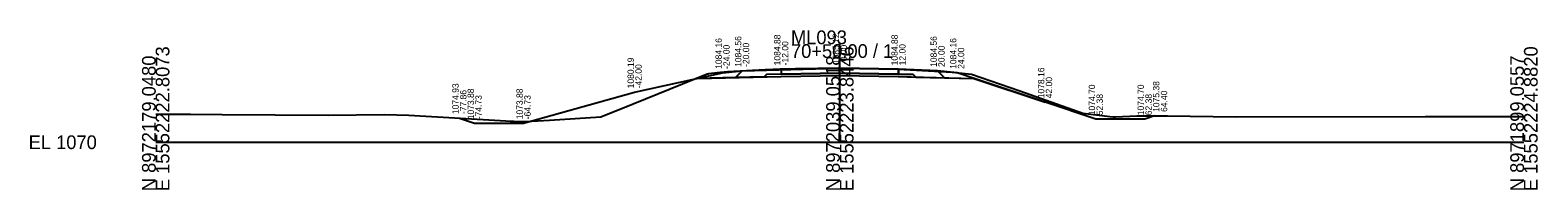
# Model space of a CAD drawing. Extents: x -26 to 14283, y -10 to 28.
# Drawn here: x 9974.3 to 10282.8, y -9.7 to 22.8 of the extents above; entities that cross this region are included whole.
import ezdxf

# ---------------------------------------------------------------- set-up
doc = ezdxf.new("R2010")
doc.units = 0
for name, color, linetype in [('Default', 7, 'Continuous'), ('dsn3DCenterLine', 7, 'Continuous'), ('dsn3DDitchBack', 7, 'Continuous'), ('dsn3DDitchFront', 7, 'Continuous'), ('dsn3DForeSlopeBarnRoofPoint', 7, 'Continuous'), ('dsn3DForeSlopeBreakLine', 7, 'Continuous'), ('dsn3DGroundLineIntercept', 7, 'Continuous'), ('dsn3DPavementTop', 7, 'Continuous'), ('dsn3DShoulderTop', 7, 'Continuous'), ('dsn3DSubgradeBreakLine', 7, 'Continuous'), ('dsn3DSubgradeHingePoint', 7, 'Continuous'), ('dsnGeopakCellCrossSection', 7, 'Continuous'), ('dsnXSEarthwork', 7, 'Continuous'), ('dsnXsExistingGround', 7, 'Continuous'), ('dsnXsPCCPavement', 7, 'Continuous'), ('dsnXsShldrEarthFill', 7, 'Continuous'), ('dsnXsShldrGranular', 7, 'Continuous'), ('dsnXsSideSlopes', 7, 'Continuous'), ('dsnXsSubbase', 7, 'Continuous'), ('dsnXsTextOffsetElevFinGrd', 7, 'Continuous')]:
    doc.layers.add(name, color=color, linetype=linetype)

msp = doc.modelspace()

# ---------------------------------------------------------------- linework, layer by layer
at = {"layer": 'Default'}
for points in [[(10110.84, 13.02), (10128, 13.38), (10140, 13.62), (10152, 13.38), (10167.42, 13.02), (10182, 8.16)], [(10120, 14.56), (10140, 15.12), (10152, 14.88), (10160, 14.56)]]:
    msp.add_lwpolyline(points, dxfattribs=at)
at = {"layer": 'dsnGeopakCellCrossSection'}
for p, q in [((10140, 0), (10140, 20)), ((10000, 0), (10140, 0)), ((10140, 0), (10280, 0))]:
    msp.add_line(p, q, dxfattribs=at)
at = {"layer": 'dsnXSEarthwork'}
msp.add_lwpolyline([(10120, 14.56), (10128, 14.88), (10140, 15.12), (10152, 14.88), (10160, 14.56)], dxfattribs=at)
at = {"layer": 'dsnXsExistingGround'}
msp.add_lwpolyline([(10000, 5.73), (10007.13, 5.71), (10013.61, 5.65), (10035.28, 5.51), (10046.8, 5.68), (10051.77, 5.52), (10071.68, 4.38), (10072.52, 4.33), (10073.26, 4.33), (10075.84, 4.25), (10080.58, 4.53), (10091.09, 5.2), (10097.74, 7.84), (10112.85, 13.92), (10113.08, 13.97), (10113.22, 14.01), (10114.91, 14.19), (10116.99, 14.4), (10124.71, 14.81), (10127.81, 14.96), (10130.94, 15.02), (10139.97, 15.19), (10149.4, 14.97), (10151.89, 14.91), (10155.67, 14.71), (10162.98, 14.32), (10165.01, 14.08), (10166.93, 13.86), (10176.81, 10.48), (10189.72, 5.91), (10195.26, 5.26), (10195.94, 5.18), (10196.38, 5.2), (10200.79, 5.38), (10203.17, 5.38), (10207.03, 5.37), (10221.04, 5.19), (10259.75, 5.22), (10265.95, 5.25), (10268.96, 5.27), (10280, 5.26)], dxfattribs=at)
at = {"layer": 'dsnXsPCCPavement'}
msp.add_lwpolyline([(10128, 14.88), (10128, 14.88), (10128, 13.88), (10128, 13.88), (10128, 13.88), (10140, 14.12), (10152, 13.88), (10152, 13.88), (10152, 13.88), (10152, 14.88), (10152, 14.88), (10140, 15.12), (10128, 14.88)], dxfattribs=at)
at = {"layer": 'dsnXsShldrEarthFill'}
for points in [[(10118.62, 13.19), (10110.84, 13.02)], [(10161.4, 13.16), (10167.42, 13.02)]]:
    msp.add_lwpolyline(points, dxfattribs=at)
at = {"layer": 'dsnXsShldrGranular'}
for points in [[(10120, 14.56), (10128, 14.88), (10128, 13.88), (10128, 13.88), (10125, 13.82), (10125, 13.82), (10124.49, 13.31), (10124.49, 13.31), (10118.62, 13.19), (10118.62, 13.19), (10118.62, 13.19), (10120, 14.56), (10120, 14.56)], [(10160, 14.56), (10152, 14.88), (10152, 13.88), (10152, 13.88), (10155, 13.82), (10155, 13.82), (10155.52, 13.3), (10155.52, 13.3), (10161.4, 13.16), (10161.4, 13.16), (10161.4, 13.16), (10160, 14.56), (10160, 14.56)]]:
    msp.add_lwpolyline(points, dxfattribs=at)
at = {"layer": 'dsnXsSideSlopes'}
for points in [[(10062.14, 4.93), (10065.27, 3.88), (10065.27, 3.88), (10075.27, 3.88), (10075.27, 3.88), (10098, 10.19), (10098, 10.19), (10098, 10.19), (10116, 14.16), (10116, 14.16), (10120, 14.56)], [(10204.4, 5.38), (10202.38, 4.7), (10202.38, 4.7), (10192.38, 4.7), (10192.38, 4.7), (10182, 8.16), (10182, 8.16), (10182, 8.16), (10164, 14.16), (10164, 14.16), (10160, 14.56)]]:
    msp.add_lwpolyline(points, dxfattribs=at)
at = {"layer": 'dsnXsSubbase'}
msp.add_lwpolyline([(10124.49, 13.31), (10124.49, 13.31), (10124.49, 13.31), (10128, 13.38), (10128, 13.38), (10140, 13.62), (10152, 13.38), (10152, 13.38), (10155.52, 13.3), (10155.52, 13.3), (10155.52, 13.3), (10155, 13.82), (10155, 13.82), (10152, 13.88), (10152, 13.88), (10140, 14.12), (10128, 13.88), (10128, 13.88), (10125, 13.82), (10125, 13.82), (10124.49, 13.31)], dxfattribs=at)

# ---------------------------------------------------------------- texts
msp.add_text('-', height=0.0001).set_placement((10000, 0))
at = {"layer": 'dsn3DCenterLine'}
msp.add_text('X', height=0.00781, dxfattribs=at).set_placement((10140, 15.12))
at = {"layer": 'dsn3DDitchBack'}
for p in [(10065.26, 3.88), (10202.38, 4.7)]:
    msp.add_text('X', height=0.00781, dxfattribs=at).set_placement(p)
at = {"layer": 'dsn3DDitchFront'}
for p in [(10075.26, 3.88), (10192.38, 4.7)]:
    msp.add_text('X', height=0.00781, dxfattribs=at).set_placement(p)
at = {"layer": 'dsn3DForeSlopeBarnRoofPoint'}
for p in [(10098, 10.18), (10182, 8.16)]:
    msp.add_text('X', height=0.00781, dxfattribs=at).set_placement(p)
at = {"layer": 'dsn3DForeSlopeBreakLine'}
for p in [(10116, 14.16), (10164, 14.16)]:
    msp.add_text('X', height=0.00781, dxfattribs=at).set_placement(p)
at = {"layer": 'dsn3DGroundLineIntercept'}
for p in [(10062.13, 4.92), (10204.39, 5.37)]:
    msp.add_text('X', height=0.00781, dxfattribs=at).set_placement(p)
at = {"layer": 'dsn3DPavementTop'}
for p in [(10128, 14.88), (10152, 14.88)]:
    msp.add_text('X', height=0.00781, dxfattribs=at).set_placement(p)
at = {"layer": 'dsn3DShoulderTop'}
for p in [(10120, 14.56), (10160, 14.56)]:
    msp.add_text('X', height=0.00781, dxfattribs=at).set_placement(p)
at = {"layer": 'dsn3DSubgradeBreakLine'}
for p in [(10128, 13.38), (10140, 13.62), (10152, 13.38)]:
    msp.add_text('X', height=0.00781, dxfattribs=at).set_placement(p)
at = {"layer": 'dsn3DSubgradeHingePoint'}
for p in [(10110.84, 13.02), (10167.42, 13.02)]:
    msp.add_text('X', height=0.00781, dxfattribs=at).set_placement(p)
at = {"layer": 'dsnGeopakCellCrossSection'}
for s, p in [('ML093', (10130, 20)), ('70+50.00 / 1', (10130, 17.2)), ('EL 1070', (9974, -1.4))]:
    msp.add_text(s, height=2.8, dxfattribs=at).set_placement(p)
for s, p in [('E 15552222.8073', (10002.8, -10)), ('E 15552223.8446', (10142.8, -10)), ('E 15552224.8820', (10282.8, -10)), ('N 8972179.0480', (10000, -10)), ('N 8972039.0518', (10140, -10)), ('N 8971899.0557', (10280, -10))]:
    msp.add_text(s, height=2.8, rotation=90, dxfattribs=at).set_placement(p)
at = {"layer": 'dsnXsTextOffsetElevFinGrd'}
for s, p in [('1084.88', (10127.85, 15.68)), ('1085.12', (10139.85, 15.92)), ('1084.88', (10151.85, 15.68)), ('1084.16', (10115.85, 14.96)), ('-24.00', (10117.45, 14.96)), ('1084.56', (10119.85, 15.36)), ('-20.00', (10121.45, 15.36)), ('-12.00', (10129.45, 15.68)), ('-0.00', (10141.45, 15.92)), ('12.00', (10153.45, 15.68)), ('1084.56', (10159.85, 15.36)), ('20.00', (10161.45, 15.36)), ('1084.16', (10163.85, 14.96)), ('24.00', (10165.45, 14.96)), ('1080.19', (10097.85, 10.99)), ('-42.00', (10099.45, 10.99)), ('1078.16', (10181.85, 8.96)), ('42.00', (10183.45, 8.96)), ('1075.38', (10205.39, 6.18)), ('1074.93', (10061.99, 5.73)), ('-77.86', (10063.59, 5.73)), ('1073.88', (10065.12, 4.68)), ('-74.73', (10066.72, 4.68)), ('1073.88', (10075.12, 4.68)), ('-64.73', (10076.72, 4.68)), ('1074.70', (10192.23, 5.5)), ('52.38', (10193.83, 5.5)), ('1074.70', (10202.23, 5.5)), ('62.38', (10203.83, 5.5)), ('64.40', (10206.99, 6.18))]:
    msp.add_text(s, height=1.3, rotation=90, dxfattribs=at).set_placement(p)

doc.saveas('drawing.dxf')
